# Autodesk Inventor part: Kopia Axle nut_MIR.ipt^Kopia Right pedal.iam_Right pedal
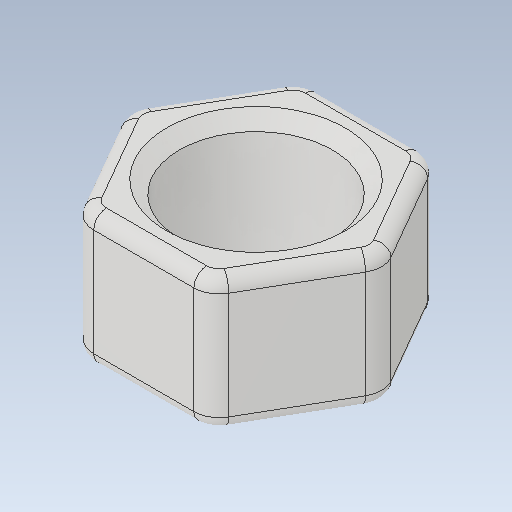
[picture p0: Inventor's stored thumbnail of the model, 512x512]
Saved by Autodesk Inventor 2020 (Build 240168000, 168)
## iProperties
Created: 2017-10
Part Number: Kopia Axle nut_MIR.ipt^Kopia Right pedal.iam_Right pedal
Material: Ogólny
Document SubType Name: Modeling
Designer: Tomasz
Density: 1 g/cm^3
Appearance: Domyślna
Sending System: SolidWorks 2017
Last Author: Tomasz
Last Saved: 2017-10-01
Author: Tomasz
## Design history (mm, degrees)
feature "Axle nut_MIR.ipt"
node "Bryła1"
